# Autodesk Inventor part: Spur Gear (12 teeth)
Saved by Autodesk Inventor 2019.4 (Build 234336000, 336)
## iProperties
Created: 2020-02
Part Number: Spur Gear (12 teeth)
Material: Generic
Description: Spur Gear; Module: 1.0; Num Teeth: 12; Pressure Angle: 20.0; Backlash: 0.00 mm
Document SubType Name: Modeling
Designer: Administrator
Density: 1 g/cm^3
Appearance: Default
Title: Spur Gear (12 teeth)
Author: Administrator
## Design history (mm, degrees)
feature "Body1"
feature "Body2"
body "Solid1"
body "Solid2"
